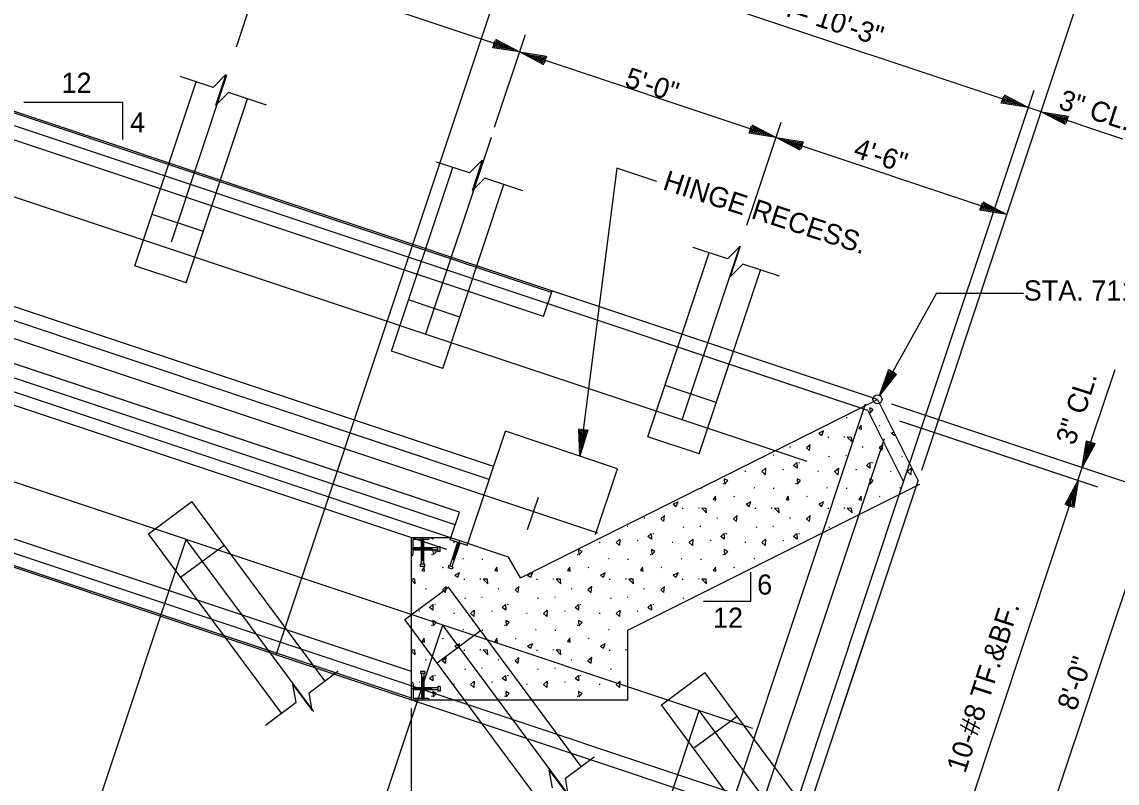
# Model space of a CAD drawing. Extents: x 6 to 106, y 3 to 74.
# Drawn here: x 51.98 to 72.23, y 45.46 to 59.53 of the extents above; entities that cross this region are included whole.
import ezdxf

# ---------------------------------------------------------------- set-up
doc = ezdxf.new("R2010")
doc.units = 0
for name, color, linetype in [('Level 13', 7, 'Continuous'), ('Level 22', 7, 'Continuous'), ('Level 25', 7, 'Continuous'), ('Level 44', 7, 'Continuous'), ('Level 50', 7, 'Continuous')]:
    doc.layers.add(name, color=color, linetype=linetype)

msp = doc.modelspace()

# ---------------------------------------------------------------- linework, layer by layer
at = {"layer": 'Level 13'}
for points in [[(55.512, 58.317), (55.748, 58.554), (55.559, 57.986), (55.796, 58.222)], [(60.254, 56.736), (60.49, 56.974), (60.301, 56.405), (60.538, 56.642)], [(65.026, 55.146), (65.262, 55.383), (65.073, 54.815), (65.31, 55.051)], [(57.048, 46.95), (56.989, 47.279), (57.346, 46.798), (57.288, 47.128)], [(61.789, 45.367), (61.73, 45.697), (62.087, 45.216), (62.03, 45.545)]]:
    msp.add_lwpolyline(points, dxfattribs=at)
at = {"layer": 'Level 22'}
for p, q in [((52.014, 58.043), (53.845, 58.043)), ((53.845, 57.355), (53.845, 58.043)), ((62.98, 56.826), (62.294, 51.502)), ((68.892, 54.512), (67.839, 52.625)), ((61.198, 49.25), (67.8, 52.551)), ((67.8, 52.551), (68.553, 51.045)), ((67.623, 52.346), (68.283, 51.026)), ((63.18, 48.284), (68.583, 50.985)), ((54.316, 50.064), (55.119, 50.66)), ((57.579, 47.344), (55.119, 50.66)), ((56.776, 46.748), (54.316, 50.064)), ((54.912, 49.261), (55.715, 49.857)), ((57.373, 46.782), (55.015, 49.961)), ((60.035, 49.905), (59.89, 49.471)), ((60.074, 49.892), (59.929, 49.457)), ((60.068, 49.938), (59.948, 49.579)), ((59.87, 49.477), (59.857, 49.438)), ((59.949, 49.451), (59.936, 49.411)), ((65.455, 48.817), (65.455, 49.355)), ((59.059, 48.483), (59.863, 49.079)), ((62.322, 45.763), (59.863, 49.079)), ((64.583, 48.817), (65.455, 48.817)), ((61.519, 45.167), (59.059, 48.483)), ((59.655, 47.68), (60.458, 48.276)), ((62.117, 45.201), (59.759, 48.379)), ((57.288, 47.128), (57.82, 47.523)), ((63.803, 46.902), (64.606, 47.498)), ((67.066, 44.181), (64.606, 47.498)), ((56.48, 46.529), (57.048, 46.95)), ((66.263, 43.586), (63.803, 46.902)), ((66.86, 43.62), (64.502, 46.798)), ((64.399, 46.099), (65.202, 46.695)), ((62.03, 45.545), (62.563, 45.941))]:
    msp.add_line(p, q, dxfattribs=at)
msp.add_circle((67.8, 52.551), 0.0833, dxfattribs=at)
for centre, start, end in [((59.483, 49.991), 270, 0), ((59.18, 49.689), 270, 0), ((59.18, 47.293), 0, 90), ((59.18, 47.293), 0, 90), ((59.483, 46.991), 0, 90), ((59.483, 46.991), 0, 90)]:
    msp.add_arc(centre, 0.0313, start, end, dxfattribs=at)
at = {"layer": 'Level 25'}
for p, q in [((61.773, 54.527), (41.171, 61.394)), ((67.8, 52.551), (41.18, 61.424)), ((59.205, 55.416), (61.228, 61.482)), ((67.623, 52.346), (41.18, 61.16)), ((70.827, 57.866), (61.103, 61.108)), ((61.625, 54.082), (41.18, 60.897)), ((55.943, 59.067), (56.57, 60.949)), ((61.182, 58.973), (56.438, 60.554)), ((68.618, 51.24), (71.534, 59.988)), ((66.501, 51.403), (41.18, 59.843)), ((60.718, 57.583), (61.289, 59.296)), ((65.925, 57.392), (61.182, 58.973)), ((54.742, 55.464), (55.768, 58.544)), ((54.067, 55.02), (55.2, 58.421)), ((55.512, 58.317), (54.901, 58.521)), ((56.5, 57.988), (55.796, 58.222)), ((68.283, 51.026), (70.697, 58.267)), ((55.015, 54.704), (56.149, 58.105)), ((60.7, 51.309), (41.18, 57.815)), ((72.339, 57.362), (70.827, 57.866)), ((60.621, 51.072), (41.18, 57.552)), ((65.386, 55.773), (66.021, 57.678)), ((60.655, 57.393), (59.443, 53.755)), ((70.194, 55.969), (65.925, 57.392)), ((62.626, 50.074), (41.18, 57.222)), ((60.254, 56.736), (59.645, 56.939)), ((60.068, 50.465), (41.18, 56.761)), ((58.81, 53.439), (59.944, 56.84)), ((63.721, 56.578), (62.98, 56.826)), ((59.759, 53.123), (60.892, 56.524)), ((61.243, 56.407), (60.538, 56.642)), ((59.989, 50.228), (41.18, 56.498)), ((59.91, 49.991), (41.101, 56.261)), ((59.837, 49.772), (41.028, 56.042)), ((55.332, 55.653), (54.383, 55.969)), ((56.676, 47.826), (59.205, 55.416)), ((64.186, 52.174), (65.248, 55.36)), ((65.026, 55.146), (64.388, 55.358)), ((63.554, 51.858), (64.687, 55.259)), ((55.015, 54.704), (54.067, 55.02)), ((64.502, 51.542), (65.636, 54.942)), ((65.986, 54.826), (65.31, 55.051)), ((65.492, 46.468), (41.18, 54.572)), ((61.625, 54.082), (61.783, 54.556)), ((68.892, 54.512), (70.503, 54.512)), ((60.075, 54.072), (59.126, 54.388)), ((59.18, 47.518), (41.18, 53.518)), ((59.759, 53.123), (58.81, 53.439)), ((66.479, 44.822), (41.18, 53.255)), ((71.588, 51.288), (72.193, 53.103)), ((66.4, 44.585), (41.18, 52.991)), ((59.18, 47.024), (41.19, 53.021)), ((64.819, 52.49), (63.87, 52.807)), ((65.149, 45.173), (67.58, 52.468)), ((73.495, 50.652), (68.065, 52.462)), ((71.872, 50.93), (68.216, 52.148)), ((60.226, 49.886), (60.918, 51.961)), ((62.993, 51.269), (60.918, 51.961)), ((64.502, 51.542), (63.554, 51.858)), ((65.633, 44.947), (67.927, 51.83)), ((62.587, 50.053), (62.993, 51.269)), ((69.059, 43.698), (71.588, 51.288)), ((66.4, 44.585), (68.553, 51.045)), ((66.162, 44.664), (68.283, 51.026)), ((61.329, 50.146), (61.528, 50.742)), ((70.45, 43.235), (72.98, 50.824)), ((59.91, 49.991), (60.068, 50.465)), ((53.213, 44.554), (55.015, 49.961)), ((59.18, 46.991), (59.18, 49.991)), ((59.91, 49.991), (59.18, 49.991)), ((59.18, 46.991), (59.18, 49.991)), ((59.91, 49.991), (59.18, 49.991)), ((59.212, 49.689), (59.212, 49.96)), ((59.483, 49.96), (59.212, 49.96)), ((59.368, 49.502), (59.368, 49.96)), ((59.389, 49.561), (59.389, 49.991)), ((59.41, 49.502), (59.41, 49.96)), ((59.896, 49.952), (59.91, 49.991)), ((60.213, 49.846), (59.896, 49.952)), ((60.975, 49.636), (59.91, 49.991)), ((60.213, 49.846), (60.226, 49.886)), ((59.562, 49.783), (59.18, 49.783)), ((59.67, 49.804), (59.212, 49.804)), ((59.67, 49.762), (59.212, 49.762)), ((59.67, 49.741), (59.67, 49.824)), ((59.712, 49.824), (59.67, 49.824)), ((59.712, 49.741), (59.67, 49.741)), ((59.712, 49.741), (59.712, 49.824)), ((61.198, 49.25), (60.975, 49.636)), ((59.43, 49.502), (59.347, 49.502)), ((59.347, 49.46), (59.347, 49.502)), ((59.43, 49.46), (59.347, 49.46)), ((59.43, 49.46), (59.43, 49.502)), ((59.936, 49.411), (59.857, 49.438)), ((59.949, 49.451), (59.87, 49.477)), ((57.935, 42.909), (59.759, 48.379)), ((63.18, 46.991), (63.18, 48.284)), ((66.4, 44.585), (67.642, 48.312)), ((59.43, 47.522), (59.347, 47.522)), ((59.347, 47.522), (59.347, 47.481)), ((59.43, 47.522), (59.347, 47.522)), ((59.347, 47.522), (59.347, 47.481)), ((59.43, 47.481), (59.347, 47.481)), ((59.43, 47.481), (59.347, 47.481)), ((59.368, 47.481), (59.368, 47.022)), ((59.368, 47.481), (59.368, 47.022)), ((59.389, 47.421), (59.389, 46.991)), ((59.389, 47.421), (59.389, 46.991)), ((59.41, 47.481), (59.41, 47.022)), ((59.41, 47.481), (59.41, 47.022)), ((59.43, 47.522), (59.43, 47.481)), ((59.43, 47.522), (59.43, 47.481)), ((59.562, 47.199), (59.18, 47.199)), ((59.562, 47.199), (59.18, 47.199)), ((59.212, 47.293), (59.212, 47.022)), ((59.212, 47.293), (59.212, 47.022)), ((59.67, 47.22), (59.212, 47.22)), ((59.67, 47.22), (59.212, 47.22)), ((59.67, 47.241), (59.67, 47.158)), ((59.712, 47.241), (59.67, 47.241)), ((59.67, 47.241), (59.67, 47.158)), ((59.712, 47.241), (59.67, 47.241)), ((59.712, 47.241), (59.712, 47.158)), ((59.712, 47.241), (59.712, 47.158)), ((59.67, 47.179), (59.212, 47.179)), ((59.67, 47.179), (59.212, 47.179)), ((59.483, 47.022), (59.212, 47.022)), ((59.483, 47.022), (59.212, 47.022)), ((59.712, 47.158), (59.67, 47.158)), ((59.712, 47.158), (59.67, 47.158)), ((63.18, 46.991), (59.18, 46.991)), ((59.18, 38.546), (59.18, 46.836)), ((62.68, 41.331), (64.502, 46.798))]:
    msp.add_line(p, q, dxfattribs=at)
at = {"layer": 'Level 44'}
for p, q in [((67.646, 52.302), (67.633, 52.303)), ((67.236, 52.212), (67.218, 52.212)), ((67.846, 52.067), (67.83, 52.059)), ((66.19, 51.665), (66.172, 51.668)), ((66.898, 51.845), (66.88, 51.845)), ((67.197, 51.852), (67.18, 51.852)), ((67.536, 51.665), (67.519, 51.668)), ((65.877, 51.514), (65.864, 51.509)), ((66.913, 51.496), (66.895, 51.491)), ((67.223, 51.514), (67.21, 51.509)), ((68.259, 51.496), (68.241, 51.491)), ((66.069, 51.249), (66.055, 51.256)), ((66.359, 51.373), (66.344, 51.382)), ((67.416, 51.249), (67.401, 51.256)), ((67.706, 51.373), (67.691, 51.382)), ((65.362, 51.217), (65.347, 51.216)), ((66.709, 51.217), (66.694, 51.216)), ((68.055, 51.217), (68.041, 51.216)), ((64.542, 50.901), (64.524, 50.901)), ((64.953, 50.99), (64.939, 50.991)), ((65.53, 50.912), (65.517, 50.914)), ((65.889, 50.901), (65.871, 50.901)), ((66.299, 50.99), (66.286, 50.991)), ((66.877, 50.912), (66.864, 50.914)), ((67.236, 50.901), (67.218, 50.901)), ((67.646, 50.99), (67.633, 50.991)), ((68.224, 50.912), (68.21, 50.914)), ((65.153, 50.755), (65.137, 50.747)), ((66.5, 50.755), (66.484, 50.747)), ((67.846, 50.755), (67.83, 50.747)), ((64.205, 50.534), (64.187, 50.534)), ((64.504, 50.54), (64.487, 50.54)), ((65.552, 50.534), (65.534, 50.534)), ((65.85, 50.54), (65.833, 50.54)), ((66.898, 50.534), (66.88, 50.534)), ((67.197, 50.54), (67.18, 50.54)), ((63.496, 50.354), (63.479, 50.357)), ((64.843, 50.354), (64.826, 50.357)), ((66.19, 50.354), (66.172, 50.357)), ((63.183, 50.203), (63.17, 50.198)), ((63.666, 50.061), (63.651, 50.07)), ((64.219, 50.185), (64.201, 50.18)), ((64.53, 50.203), (64.517, 50.198)), ((65.013, 50.061), (64.998, 50.07)), ((65.566, 50.185), (65.548, 50.18)), ((65.877, 50.203), (65.864, 50.198)), ((66.359, 50.061), (66.344, 50.07)), ((66.913, 50.185), (66.895, 50.18)), ((59.336, 49.937), (59.321, 49.944)), ((59.975, 49.905), (59.961, 49.904)), ((62.669, 49.905), (62.654, 49.904)), ((63.376, 49.937), (63.361, 49.944)), ((64.015, 49.905), (64.001, 49.904)), ((64.722, 49.937), (64.708, 49.944)), ((65.362, 49.905), (65.347, 49.904)), ((66.069, 49.937), (66.055, 49.944)), ((59.566, 49.678), (59.553, 49.679)), ((62.259, 49.678), (62.246, 49.679)), ((63.606, 49.678), (63.593, 49.679)), ((64.953, 49.678), (64.939, 49.679)), ((59.766, 49.443), (59.75, 49.435)), ((60.144, 49.6), (60.13, 49.603)), ((60.502, 49.589), (60.484, 49.589)), ((62.46, 49.443), (62.444, 49.435)), ((62.837, 49.6), (62.824, 49.603)), ((63.196, 49.589), (63.178, 49.589)), ((63.806, 49.443), (63.79, 49.435)), ((64.184, 49.6), (64.17, 49.603)), ((64.542, 49.589), (64.524, 49.589)), ((65.153, 49.443), (65.137, 49.435)), ((65.53, 49.6), (65.517, 49.603)), ((60.165, 49.222), (60.147, 49.222)), ((60.464, 49.228), (60.447, 49.228)), ((61.512, 49.222), (61.494, 49.222)), ((61.81, 49.228), (61.793, 49.228)), ((62.858, 49.222), (62.84, 49.222)), ((63.157, 49.228), (63.14, 49.228)), ((64.205, 49.222), (64.187, 49.222)), ((64.504, 49.228), (64.487, 49.228)), ((59.456, 49.042), (59.439, 49.045)), ((60.803, 49.042), (60.786, 49.045)), ((62.15, 49.042), (62.132, 49.045)), ((63.496, 49.042), (63.479, 49.045)), ((60.179, 48.873), (60.161, 48.868)), ((60.49, 48.891), (60.477, 48.886)), ((61.526, 48.873), (61.508, 48.868)), ((61.837, 48.891), (61.824, 48.886)), ((62.873, 48.873), (62.855, 48.868)), ((63.183, 48.891), (63.17, 48.886)), ((64.219, 48.873), (64.201, 48.868)), ((59.336, 48.626), (59.321, 48.632)), ((59.626, 48.75), (59.611, 48.759)), ((60.682, 48.626), (60.668, 48.632)), ((60.973, 48.75), (60.958, 48.759)), ((62.029, 48.626), (62.015, 48.632)), ((62.319, 48.75), (62.304, 48.759)), ((63.376, 48.626), (63.361, 48.632)), ((63.666, 48.75), (63.651, 48.759)), ((59.975, 48.594), (59.961, 48.592)), ((61.322, 48.594), (61.307, 48.592)), ((62.669, 48.594), (62.654, 48.592)), ((59.566, 48.367), (59.553, 48.368)), ((60.144, 48.289), (60.13, 48.291)), ((60.502, 48.277), (60.484, 48.277)), ((60.913, 48.367), (60.899, 48.368)), ((61.49, 48.289), (61.477, 48.291)), ((61.849, 48.277), (61.831, 48.277)), ((62.259, 48.367), (62.246, 48.368)), ((62.837, 48.289), (62.824, 48.291)), ((63.18, 48.277), (63.178, 48.277)), ((59.766, 48.132), (59.75, 48.124)), ((61.113, 48.132), (61.097, 48.124)), ((62.46, 48.132), (62.444, 48.124)), ((60.165, 47.91), (60.147, 47.91)), ((60.464, 47.917), (60.447, 47.917)), ((61.512, 47.91), (61.494, 47.91)), ((61.81, 47.917), (61.793, 47.917)), ((62.858, 47.91), (62.84, 47.91)), ((63.157, 47.917), (63.14, 47.917)), ((59.456, 47.73), (59.439, 47.733)), ((60.803, 47.73), (60.786, 47.733)), ((62.15, 47.73), (62.132, 47.733)), ((59.626, 47.438), (59.611, 47.447)), ((60.179, 47.561), (60.161, 47.556)), ((60.49, 47.579), (60.477, 47.574)), ((60.973, 47.438), (60.958, 47.447)), ((61.526, 47.561), (61.508, 47.556)), ((61.837, 47.579), (61.824, 47.574)), ((62.319, 47.438), (62.304, 47.447)), ((62.873, 47.561), (62.855, 47.556)), ((63.18, 47.578), (63.17, 47.574)), ((59.336, 47.314), (59.321, 47.321)), ((59.975, 47.282), (59.961, 47.281)), ((60.682, 47.314), (60.668, 47.321)), ((61.322, 47.282), (61.307, 47.281)), ((62.029, 47.314), (62.015, 47.321)), ((62.669, 47.282), (62.654, 47.281)), ((59.566, 47.055), (59.553, 47.056)), ((60.913, 47.055), (60.899, 47.056)), ((62.259, 47.055), (62.246, 47.056))]:
    msp.add_line(p, q, dxfattribs=at)
for points in [[(67.665, 52.297), (67.722, 52.361), (67.659, 52.395)], [(67.505, 51.999), (67.496, 52.072), (67.455, 52.011)], [(66.772, 51.884), (66.804, 51.966), (66.716, 51.923)], [(66.554, 51.713), (66.485, 51.654), (66.542, 51.606)], [(67.322, 51.847), (67.242, 51.852), (67.329, 51.763)], [(67.9, 51.713), (67.832, 51.654), (67.889, 51.606)], [(65.722, 51.158), (65.661, 51.215), (65.729, 51.276)], [(66.312, 51.279), (66.248, 51.327), (66.309, 51.381)], [(67.069, 51.158), (67.007, 51.215), (67.076, 51.276)], [(67.659, 51.279), (67.595, 51.327), (67.656, 51.381)], [(68.416, 51.158), (68.354, 51.215), (68.422, 51.276)], [(64.972, 50.985), (65.029, 51.049), (64.965, 51.083)], [(66.319, 50.985), (66.376, 51.049), (66.312, 51.083)], [(67.665, 50.985), (67.722, 51.049), (67.659, 51.083)], [(64.079, 50.573), (64.111, 50.654), (64.022, 50.611)], [(64.812, 50.687), (64.802, 50.76), (64.761, 50.699)], [(65.426, 50.573), (65.457, 50.654), (65.369, 50.611)], [(66.158, 50.687), (66.149, 50.76), (66.108, 50.699)], [(66.772, 50.573), (66.804, 50.654), (66.716, 50.611)], [(67.505, 50.687), (67.496, 50.76), (67.455, 50.699)], [(64.629, 50.536), (64.549, 50.54), (64.635, 50.451)], [(65.975, 50.536), (65.895, 50.54), (65.982, 50.451)], [(67.322, 50.536), (67.242, 50.54), (67.329, 50.451)], [(63.86, 50.402), (63.792, 50.342), (63.849, 50.294)], [(65.207, 50.402), (65.139, 50.342), (65.195, 50.294)], [(66.554, 50.402), (66.485, 50.342), (66.542, 50.294)], [(63.619, 49.967), (63.555, 50.015), (63.616, 50.07)], [(64.965, 49.967), (64.901, 50.015), (64.963, 50.07)], [(66.312, 49.967), (66.248, 50.015), (66.309, 50.07)], [(63.029, 49.847), (62.967, 49.904), (63.036, 49.965)], [(64.376, 49.847), (64.314, 49.904), (64.382, 49.965)], [(65.722, 49.847), (65.661, 49.904), (65.729, 49.965)], [(59.585, 49.674), (59.642, 49.738), (59.579, 49.772)], [(62.279, 49.674), (62.336, 49.738), (62.272, 49.772)], [(63.625, 49.674), (63.682, 49.738), (63.619, 49.772)], [(64.972, 49.674), (65.029, 49.738), (64.965, 49.772)], [(59.425, 49.376), (59.416, 49.449), (59.375, 49.388)], [(60.772, 49.376), (60.762, 49.449), (60.721, 49.388)], [(62.118, 49.376), (62.109, 49.449), (62.068, 49.388)], [(63.465, 49.376), (63.456, 49.449), (63.415, 49.388)], [(64.812, 49.376), (64.802, 49.449), (64.761, 49.388)], [(60.039, 49.261), (60.071, 49.343), (59.982, 49.3)], [(60.589, 49.224), (60.509, 49.228), (60.595, 49.14)], [(61.386, 49.261), (61.417, 49.343), (61.329, 49.3)], [(61.935, 49.224), (61.855, 49.228), (61.942, 49.14)], [(62.732, 49.261), (62.764, 49.343), (62.676, 49.3)], [(63.282, 49.224), (63.202, 49.228), (63.289, 49.14)], [(64.079, 49.261), (64.111, 49.343), (64.022, 49.3)], [(64.629, 49.224), (64.549, 49.228), (64.635, 49.14)], [(59.82, 49.09), (59.752, 49.03), (59.809, 48.983)], [(61.167, 49.09), (61.099, 49.03), (61.155, 48.983)], [(62.514, 49.09), (62.445, 49.03), (62.502, 48.983)], [(63.86, 49.09), (63.792, 49.03), (63.849, 48.983)], [(59.579, 48.655), (59.515, 48.704), (59.576, 48.758)], [(60.336, 48.535), (60.274, 48.592), (60.342, 48.653)], [(60.925, 48.655), (60.861, 48.704), (60.923, 48.758)], [(61.682, 48.535), (61.621, 48.592), (61.689, 48.653)], [(62.272, 48.655), (62.208, 48.704), (62.269, 48.758)], [(63.029, 48.535), (62.967, 48.592), (63.036, 48.653)], [(63.619, 48.655), (63.555, 48.704), (63.616, 48.758)], [(59.585, 48.362), (59.642, 48.426), (59.579, 48.46)], [(60.932, 48.362), (60.989, 48.426), (60.925, 48.46)], [(62.279, 48.362), (62.336, 48.426), (62.272, 48.46)], [(59.425, 48.064), (59.416, 48.137), (59.375, 48.076)], [(60.039, 47.949), (60.071, 48.031), (59.982, 47.988)], [(60.772, 48.064), (60.762, 48.137), (60.721, 48.076)], [(61.386, 47.949), (61.417, 48.031), (61.329, 47.988)], [(62.118, 48.064), (62.109, 48.137), (62.068, 48.076)], [(62.732, 47.949), (62.764, 48.031), (62.676, 47.988)], [(60.589, 47.912), (60.509, 47.917), (60.595, 47.828)], [(61.935, 47.912), (61.855, 47.917), (61.942, 47.828)], [(59.82, 47.778), (59.752, 47.719), (59.809, 47.671)], [(61.167, 47.778), (61.099, 47.719), (61.155, 47.671)], [(62.514, 47.778), (62.445, 47.719), (62.502, 47.671)], [(59.579, 47.344), (59.515, 47.392), (59.576, 47.446)], [(60.925, 47.344), (60.861, 47.392), (60.923, 47.446)], [(62.272, 47.344), (62.208, 47.392), (62.269, 47.446)], [(60.336, 47.223), (60.274, 47.28), (60.342, 47.341)], [(61.682, 47.223), (61.621, 47.28), (61.689, 47.341)], [(63.029, 47.223), (62.967, 47.28), (63.036, 47.341)], [(59.585, 47.05), (59.642, 47.114), (59.579, 47.148)], [(60.932, 47.05), (60.989, 47.114), (60.925, 47.148)], [(62.279, 47.05), (62.336, 47.114), (62.272, 47.148)]]:
    msp.add_lwpolyline(points, close=True, dxfattribs=at)
for points in [[(68.104, 51.943), (68.062, 51.923), (68.119, 51.884)], [(68.119, 51.884), (68.125, 51.901)], [(59.579, 49.967), (59.547, 49.991)], [(59.578, 49.991), (59.579, 49.967)], [(60.336, 49.847), (60.332, 49.85)], [(60.336, 49.849), (60.336, 49.847)], [(59.242, 49.224), (59.18, 49.227)], [(59.18, 49.21), (59.249, 49.14), (59.242, 49.224)], [(59.242, 47.912), (59.18, 47.916)], [(59.18, 47.898), (59.249, 47.828), (59.242, 47.912)]]:
    msp.add_lwpolyline(points, dxfattribs=at)
at = {"layer": 'Level 50'}
for p, q in [((61.05, 59.017), (61.05, 59.017)), ((61.182, 58.973), (61.182, 58.973)), ((61.182, 58.973), (61.182, 58.973)), ((61.313, 58.929), (61.313, 58.929)), ((70.458, 57.989), (70.458, 57.989)), ((70.59, 57.945), (70.59, 57.945)), ((70.827, 57.866), (70.827, 57.866)), ((70.958, 57.822), (70.958, 57.822)), ((65.794, 57.436), (65.794, 57.436)), ((65.925, 57.392), (65.925, 57.392)), ((65.925, 57.392), (65.925, 57.392)), ((66.057, 57.348), (66.057, 57.348)), ((70.063, 56.013), (70.063, 56.013)), ((70.194, 55.969), (70.194, 55.969)), ((67.906, 52.746), (67.906, 52.746)), ((67.839, 52.625), (67.839, 52.625)), ((62.294, 51.502), (62.294, 51.502)), ((62.312, 51.64), (62.312, 51.64)), ((71.588, 51.288), (71.588, 51.288)), ((71.632, 51.419), (71.632, 51.419)), ((71.509, 51.051), (71.509, 51.051)), ((71.466, 50.919), (71.466, 50.919))]:
    msp.add_line(p, q, dxfattribs=at)
for points in [[(60.735, 59.209), (61.182, 58.973), (60.683, 59.052), (60.727, 59.186), (61.05, 59.017), (60.711, 59.071), (60.74, 59.157), (60.924, 59.059), (60.74, 59.089), (60.752, 59.125), (60.792, 59.103)], [(61.629, 58.737), (61.182, 58.973), (61.681, 58.894), (61.636, 58.76), (61.313, 58.929), (61.652, 58.875), (61.624, 58.789), (61.44, 58.887), (61.624, 58.857), (61.612, 58.821), (61.571, 58.843)], [(70.143, 58.181), (70.59, 57.945), (70.09, 58.025), (70.135, 58.159), (70.458, 57.989), (70.119, 58.043), (70.148, 58.129), (70.332, 58.031), (70.148, 58.062), (70.16, 58.097), (70.2, 58.075)], [(71.274, 57.63), (70.827, 57.866), (71.326, 57.787), (71.281, 57.653), (70.958, 57.822), (71.297, 57.768), (71.269, 57.682), (71.085, 57.78), (71.269, 57.75), (71.257, 57.714), (71.216, 57.736)], [(65.478, 57.628), (65.925, 57.392), (65.426, 57.471), (65.471, 57.605), (65.794, 57.436), (65.455, 57.49), (65.483, 57.576), (65.667, 57.478), (65.483, 57.508), (65.495, 57.544), (65.536, 57.522)], [(66.372, 57.156), (65.925, 57.392), (66.424, 57.313), (66.38, 57.179), (66.057, 57.348), (66.396, 57.294), (66.367, 57.208), (66.183, 57.306), (66.367, 57.276), (66.355, 57.24), (66.315, 57.262)], [(69.747, 56.205), (70.194, 55.969), (69.695, 56.048), (69.74, 56.182), (70.063, 56.013), (69.724, 56.067), (69.752, 56.153), (69.936, 56.055), (69.752, 56.085), (69.764, 56.121), (69.805, 56.099)], [(68.154, 53.02), (67.839, 52.625), (68.01, 53.1), (68.133, 53.031), (67.906, 52.746), (68.022, 53.069), (68.102, 53.024), (67.971, 52.862), (68.035, 53.037), (68.068, 53.019), (68.039, 52.983)], [(62.44, 51.986), (62.294, 51.502), (62.276, 52.007), (62.416, 51.989), (62.312, 51.64), (62.3, 51.983), (62.39, 51.971), (62.329, 51.772), (62.324, 51.958), (62.361, 51.953), (62.347, 51.909)], [(71.825, 51.735), (71.588, 51.288), (71.668, 51.787), (71.802, 51.742), (71.632, 51.419), (71.686, 51.758), (71.772, 51.73), (71.674, 51.546), (71.705, 51.73), (71.74, 51.718), (71.718, 51.677)], [(71.273, 50.604), (71.509, 51.051), (71.43, 50.551), (71.296, 50.596), (71.466, 50.919), (71.412, 50.58), (71.326, 50.609), (71.423, 50.793), (71.393, 50.609), (71.358, 50.621), (71.38, 50.661)]]:
    msp.add_lwpolyline(points, dxfattribs=at)

# ---------------------------------------------------------------- texts
at = {"layer": 'Level 22'}
for s, height, rotation, p in [('#6, 6" TF.&BF.= 10\'-3"', 0.37333, 342, (63.092, 60.616)), ('5\'-0"', 0.3733, 342, (63.104, 58.343)), ('3" CL.', 0.3733, 342, (71.127, 57.932)), ('4\'-6"', 0.3733, 342, (67.332, 57.037)), ('HINGE RECESS.', 0.37333, 342, (63.809, 56.439)), ('3" CL.', 0.3733, 72, (71.444, 51.686)), ('10-#8 TF.&BF.', 0.37333, 72, (69.423, 45.624)), ('8\'-0"', 0.3733, 72, (71.469, 46.774))]:
    msp.add_text(s, height=height, rotation=rotation, dxfattribs=at).set_placement(p)
for s, height, p in [('12', 0.3733, (52.709, 58.217)), ('4', 0.373, (53.978, 57.486)), ('STA. 711+16.11 W/L', 0.37333, (70.505, 54.377)), ('6', 0.373, (65.575, 48.941)), ('12', 0.3733, (64.757, 48.327))]:
    msp.add_text(s, height=height, dxfattribs=at).set_placement(p)

doc.saveas('drawing.dxf')
